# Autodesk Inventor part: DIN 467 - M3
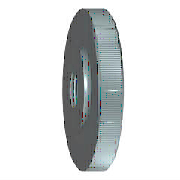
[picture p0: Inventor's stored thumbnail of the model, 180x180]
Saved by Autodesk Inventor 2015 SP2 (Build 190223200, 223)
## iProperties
IsCustomPart: 0
Created: 2012-02
Part Number: DIN 467 - M3
Material: Stahl, weich
Description: Rändelmutter
Document SubType Name: Modeling
Standard: DIN 467
Designer: rYan
Standards Organization: DIN
Language: de-DE
Size Designation: M3
Categories: <MemberInstance><Categories><Category DisplayName="Verbindungselemente" InternalName="e4da775c-781d-43d5-af7c-5136215cf5a6" Mnemonic="FSTN"><Category DisplayNam
Density: 7.85 g/cm^3
Mass: 2.19934 g
Surface Area: 3.25278 cm^2
Volume: 0.280171 cm^3
Appearance: Halbpoliert
Author: rYan
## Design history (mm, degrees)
body "Solid1"
revolve "Körper" stored, may be unused: angle "d8" = 90 deg
sketch "Skizze2"
  geometry: L1 (0, 0)-(0, 6); L2 (-0.25, 5.995)-(0, 5.745); L3 (0.25, 5.995)-(0, 5.745); C1 r 3 at (0, 0) reference; A1 r 6 centre (0, 0) between (0, 6) and (-0.25, 5.995) reference; A2 r 6 centre (0, 0) between (0.25, 5.995) and (-0.25, 5.995); 1 further point
  constraints: 6 end point, 5 point on circle, 1 centre point, 1 coincident, 1 point on line, 1 symmetric about line, 1 vertical, 1 other
  dimensions: "d4" = 90 deg angle of L3 L2; "d5" = 0.25 distance from line of L1 L2.start (= 0.5 x T)
chamfer "Fase1" distance "d13" = 0.3 (= PHH); stored, may be unused: angle "d15" = 45 deg (= FAWI), second distance "d36" = 0.3 (= PHH)
chamfer "Fase2" distance "d23" = 0.3 (= PHH); stored, may be unused: angle "d24" = 45 deg (= FAWI), second distance "d37" = 0.3 (= PHH)
extrude "Nut1" cut sketch "Skizze2" taper "d6" = 0 deg; stored distance "d11" = 10
pattern_circular "Nuten1" dims angle "d9" = 360 deg
hole "Gewinde" sketch "Skizze2" diameter "d16" = 2.459; stored, may be unused: countersink angle "d20" = 82 deg, drill point angle "d22" = 118 deg; dims "d17" = 6, "d18" = 4, "d19" = 2, "d21" = 8
chamfer "Fase3" distance "d10" = 0.27063 (= -0.5 x GD1 + 0.5 x NND); stored, may be unused: angle "d12" = 30 deg, second distance "d38" = 0.27063 (= -0.5 x GD1 + 0.5 x NND)
workaxis "Work Axis1"
workplane "Work Plane1"
sketch "Skizze1"
  geometry: L1 (0, 0)-(-3, 0) reference; L2 (0, 0)-(0, 6) reference; L3 (0, 6)-(-2.5, 6); L4 (-2.5, 6)-(-2.5, 3.5); L5 (-3, 3)-(-3, 3); L6 (-3, 3)-(-3, 0); A1 r 0.5 centre (-3, 3.5) between (-3, 3) and (-2.5, 3.5)
  constraints: 12 end point, 5 perpendicular, 2 horizontal, 2 point on circle, 2 tangent, 1 centre point, 1 point on line, 1 vertical
  dimensions: "d0" = 0.5 radius of A1 (= RR); "d1" = 3 distance of L1.start L1.end (= KOH); "d2" = 12 diameter of L3 L1 (= KOD); "d3" = 6 diameter of L5.end L1 (= BDM)
other parameters: "FAWI" = 45 deg [user parameter; used in 2 equation terms], "T" = 0.5 [user parameter; used in 2 equation terms], "NND" = 3 [user parameter; used in 2 equation terms], "KOD" = 12 [user parameter; used in 2 equation terms], "KOH" = 3 [user parameter; used in 1 equation term], "KOH1" = 2.5 [user parameter], "BDM" = 6 [user parameter; used in 1 equation term], "PHH" = 0.3 [user parameter; used in 4 equation terms], "GD1" = 2.45873 (computed from THREADDIA, PTC, TOA) [user parameter; used in 2 equation terms], "d25" = 0, "d26" = 0, "RR" = 0.5 [user parameter; used in 1 equation term], "d27" = 0, "d39" = 0, "GUL" = 0.27063 (= 0.541266 x PTC) [user parameter], "THREADDIA" = 3 [user parameter; used in 1 equation term], "TOA" = 30 deg [user parameter; used in 1 equation term], "PTC" = 0.5 [user parameter; used in 4 equation terms], "GAL" = 0.27063 (= 0.541266 x PTC) [user parameter]
